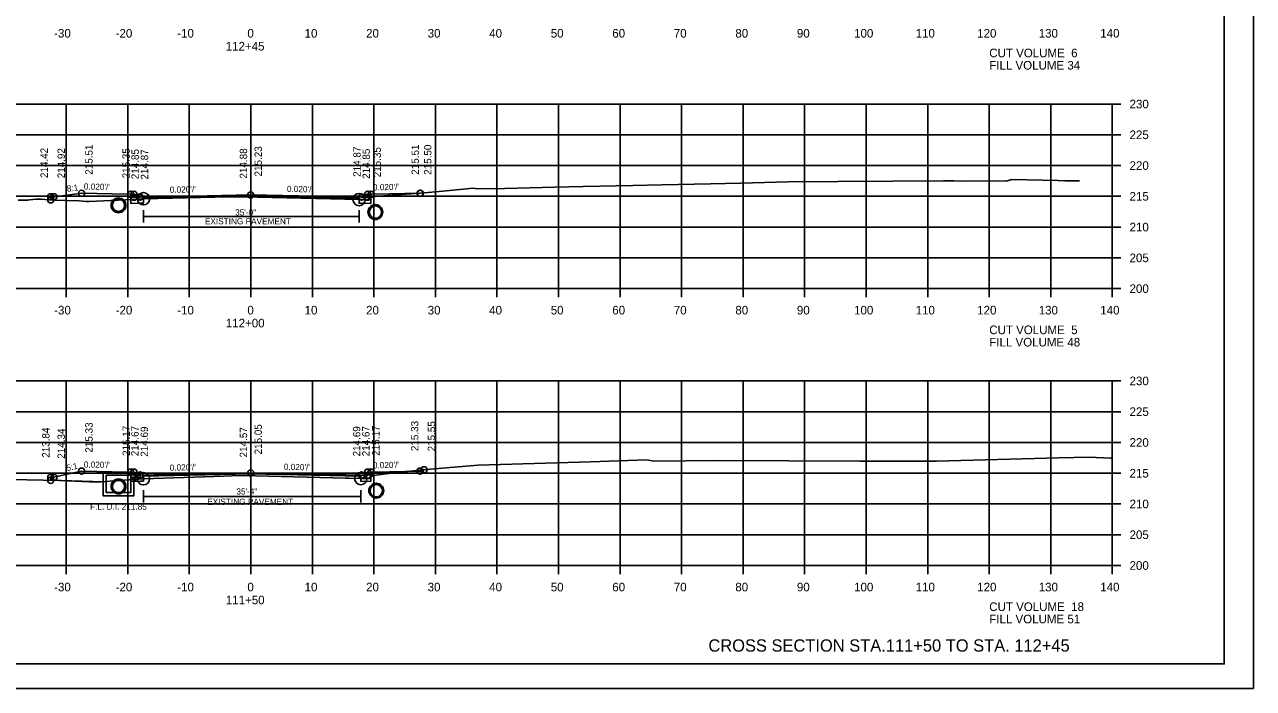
# Model space of a CAD drawing. Extents: x 1368968 to 1369915, y 377395 to 380381.
# Drawn here: x 1369715 to 1369914.7, y 377608 to 377715.9 of the extents above; entities that cross this region are included whole.
import ezdxf

# ---------------------------------------------------------------- set-up
doc = ezdxf.new("R2010")
doc.units = 0
for name, color, linetype in [('Default', 7, 'Continuous'), ('S_BORDER_NO_PLOT', 7, 'Continuous'), ('S_BREAKLINE_ANNOT', 7, 'Continuous'), ('S_BRIDGE', 7, 'Continuous'), ('S_BRIDGE_ANNOT', 7, 'Continuous'), ('S_CONTOUR_MINOR', 7, 'Continuous'), ('S_CROSS_DRAIN', 7, 'Continuous'), ('S_CTL_TABLE', 7, 'Continuous'), ('S_CURB_ANNOT', 7, 'Continuous'), ('S_DITCHLINE_ANNOT', 7, 'Continuous'), ('S_DROP_INLET', 7, 'Continuous'), ('S_EXIST_ROW_ANNOT', 7, 'Continuous'), ('S_EXISTING_ALIGNMENT_ANNOT', 7, 'Continuous'), ('S_FENCE', 7, 'Continuous')]:
    doc.layers.add(name, color=color, linetype=linetype)

msp = doc.modelspace()

# ---------------------------------------------------------------- linework, layer by layer
at = {"layer": 'Default'}
for p, q in [((1369734.35, 377687.73), (1369734.35, 377686.9)), ((1369734.32, 377642.55), (1369734.32, 377641.72))]:
    msp.add_line(p, q, dxfattribs=at)
at = {"layer": 'S_BORDER_NO_PLOT'}
for points in [[(1369732.27, 377688.36), (1369732.28, 377686.85), (1369733.78, 377686.88), (1369734.35, 377686.9), (1369734.35, 377687.73), (1369751.78, 377688.07), (1369769.37, 377687.72), (1369769.37, 377686.89), (1369769.78, 377686.88), (1369771.28, 377686.85), (1369771.29, 377688.36)], [(1369732.27, 377643.19), (1369732.28, 377641.68), (1369733.78, 377641.71), (1369734.32, 377641.72), (1369734.32, 377642.55), (1369751.78, 377642.9), (1369769.64, 377642.54), (1369769.64, 377641.71), (1369769.78, 377641.71), (1369771.28, 377641.68), (1369771.29, 377643.19)]]:
    msp.add_lwpolyline(points, dxfattribs=at)
at = {"layer": 'S_BREAKLINE_ANNOT'}
for p, q in [((1369891.78, 377673.01), (1369891.78, 377703.01)), ((1369893.18, 377703.01), (1369891.78, 377703.01)), ((1369893.18, 377698.01), (1369891.78, 377698.01)), ((1369893.18, 377693.01), (1369891.78, 377693.01)), ((1369893.18, 377688.01), (1369891.78, 377688.01)), ((1369893.18, 377683.01), (1369891.78, 377683.01)), ((1369893.18, 377678.01), (1369891.78, 377678.01)), ((1369611.78, 377673.01), (1369891.78, 377673.01)), ((1369721.78, 377671.61), (1369721.78, 377673.01)), ((1369731.78, 377671.61), (1369731.78, 377673.01)), ((1369741.78, 377671.61), (1369741.78, 377673.01)), ((1369751.78, 377671.61), (1369751.78, 377673.01)), ((1369761.78, 377671.61), (1369761.78, 377673.01)), ((1369771.78, 377671.61), (1369771.78, 377673.01)), ((1369781.78, 377671.61), (1369781.78, 377673.01)), ((1369791.78, 377671.61), (1369791.78, 377673.01)), ((1369801.78, 377671.61), (1369801.78, 377673.01)), ((1369811.78, 377671.61), (1369811.78, 377673.01)), ((1369821.78, 377671.61), (1369821.78, 377673.01)), ((1369831.78, 377671.61), (1369831.78, 377673.01)), ((1369841.78, 377671.61), (1369841.78, 377673.01)), ((1369851.78, 377671.61), (1369851.78, 377673.01)), ((1369861.78, 377671.61), (1369861.78, 377673.01)), ((1369871.78, 377671.61), (1369871.78, 377673.01)), ((1369881.78, 377671.61), (1369881.78, 377673.01)), ((1369891.78, 377671.61), (1369891.78, 377673.01)), ((1369893.18, 377673.01), (1369891.78, 377673.01)), ((1369891.78, 377628.01), (1369891.78, 377658.01)), ((1369893.18, 377658.01), (1369891.78, 377658.01)), ((1369893.18, 377653.01), (1369891.78, 377653.01)), ((1369893.18, 377648.01), (1369891.78, 377648.01)), ((1369893.18, 377643.01), (1369891.78, 377643.01)), ((1369893.18, 377638.01), (1369891.78, 377638.01)), ((1369893.18, 377633.01), (1369891.78, 377633.01)), ((1369611.78, 377628.01), (1369891.78, 377628.01)), ((1369721.78, 377626.61), (1369721.78, 377628.01)), ((1369731.78, 377626.61), (1369731.78, 377628.01)), ((1369741.78, 377626.61), (1369741.78, 377628.01)), ((1369751.78, 377626.61), (1369751.78, 377628.01)), ((1369761.78, 377626.61), (1369761.78, 377628.01)), ((1369771.78, 377626.61), (1369771.78, 377628.01)), ((1369781.78, 377626.61), (1369781.78, 377628.01)), ((1369791.78, 377626.61), (1369791.78, 377628.01)), ((1369801.78, 377626.61), (1369801.78, 377628.01)), ((1369811.78, 377626.61), (1369811.78, 377628.01)), ((1369821.78, 377626.61), (1369821.78, 377628.01)), ((1369831.78, 377626.61), (1369831.78, 377628.01)), ((1369841.78, 377626.61), (1369841.78, 377628.01)), ((1369851.78, 377626.61), (1369851.78, 377628.01)), ((1369861.78, 377626.61), (1369861.78, 377628.01)), ((1369871.78, 377626.61), (1369871.78, 377628.01)), ((1369881.78, 377626.61), (1369881.78, 377628.01)), ((1369891.78, 377626.61), (1369891.78, 377628.01)), ((1369893.18, 377628.01), (1369891.78, 377628.01))]:
    msp.add_line(p, q, dxfattribs=at)
at = {"layer": 'S_BRIDGE_ANNOT'}
for p, q in [((1369909.96, 377612.01), (1369909.96, 377817.47)), ((1369719.27, 377641.86), (1369727.8, 377641.62)), ((1369909.96, 377612.01), (1369593.78, 377612.01))]:
    msp.add_line(p, q, dxfattribs=at)
at = {"layer": 'S_CROSS_DRAIN'}
for p, q in [((1369734.35, 377684.74), (1369760.66, 377684.74)), ((1369734.35, 377684.74), (1369769.37, 377684.74)), ((1369734.32, 377639.25), (1369760.64, 377639.25)), ((1369734.32, 377639.25), (1369769.64, 377639.25))]:
    msp.add_line(p, q, dxfattribs=at)
at = {"layer": 'S_CTL_TABLE'}
for points in [[(1369713.95, 377687.36), (1369715.55, 377687.38), (1369715.81, 377687.42), (1369716.89, 377687.55), (1369717.76, 377687.53), (1369719.61, 377687.41), (1369723.9, 377687.26), (1369725.06, 377687.15), (1369725.53, 377687.18), (1369731.41, 377687.43), (1369734.35, 377687.61), (1369745.94, 377687.86), (1369750.46, 377687.93), (1369764.74, 377687.58), (1369769.37, 377687.49), (1369770.44, 377687.48), (1369770.77, 377687.48), (1369770.89, 377687.59), (1369771.32, 377687.95), (1369774.67, 377688.21), (1369777.05, 377688.34), (1369780.02, 377688.56), (1369782.96, 377688.87), (1369787.89, 377689.32), (1369788.58, 377689.21), (1369792.98, 377689.3), (1369801.21, 377689.49), (1369805.78, 377689.59), (1369813.85, 377689.78), (1369818.57, 377689.88), (1369826.5, 377690.06), (1369831.35, 377690.16), (1369839.15, 377690.34), (1369847.19, 377690.41), (1369856.12, 377690.47), (1369864.35, 377690.54), (1369866.02, 377690.55), (1369867.22, 377690.5), (1369873.49, 377690.54), (1369874.53, 377690.5), (1369875.45, 377690.74), (1369882.94, 377690.56), (1369884.05, 377690.51), (1369885.7, 377690.51), (1369886.42, 377690.52)], [(1369712.75, 377642.01), (1369720.68, 377641.83), (1369720.75, 377641.82), (1369720.77, 377641.82), (1369726.78, 377641.56), (1369728.9, 377641.71), (1369734.32, 377642.12), (1369747.38, 377642.53), (1369750, 377642.62), (1369752.6, 377642.57), (1369767.16, 377642.21), (1369767.72, 377642.2), (1369769.64, 377642.14), (1369770.79, 377642.15), (1369771.01, 377642.15), (1369771.58, 377642.56), (1369771.69, 377642.64), (1369773.75, 377642.89), (1369779.7, 377643.54), (1369788.06, 377644.29), (1369788.66, 377644.34), (1369790.52, 377644.39), (1369806.99, 377644.88), (1369816.16, 377645.17), (1369817.29, 377644.97), (1369827.65, 377645.06), (1369850.77, 377644.97), (1369863.22, 377644.99), (1369883.11, 377645.52), (1369888.01, 377645.63), (1369891.47, 377645.48), (1369891.78, 377645.47)]]:
    msp.add_lwpolyline(points, dxfattribs=at)
at = {"layer": 'S_CURB_ANNOT'}
for points in [[(1369719.27, 377687.44), (1369719.27, 377687.94), (1369719.77, 377687.94), (1369721.57, 377688.17), (1369724.27, 377688.52), (1369729.27, 377688.42), (1369732.27, 377688.36), (1369732.42, 377688.36), (1369732.77, 377688.36), (1369732.78, 377687.86), (1369733.78, 377687.88), (1369733.78, 377687.88), (1369744.69, 377688.1), (1369751.78, 377688.24), (1369769.78, 377687.88), (1369770.78, 377687.86), (1369770.78, 377688.22), (1369770.79, 377688.36), (1369770.82, 377688.36), (1369771.29, 377688.36), (1369774.29, 377688.42), (1369779.29, 377688.52), (1369779.32, 377688.51), (1369779.33, 377688.51)], [(1369719.27, 377641.86), (1369719.27, 377642.36), (1369719.77, 377642.36), (1369721.94, 377642.84), (1369724.27, 377643.35), (1369729.27, 377643.25), (1369732.27, 377643.19), (1369732.4, 377643.19), (1369732.77, 377643.19), (1369732.78, 377642.69), (1369733.78, 377642.71), (1369745.28, 377642.94), (1369751.77, 377643.07), (1369751.78, 377643.07), (1369769.78, 377642.71), (1369770.78, 377642.69), (1369770.78, 377642.88), (1369770.79, 377643.19), (1369770.86, 377643.19), (1369771.29, 377643.19), (1369774.29, 377643.25), (1369779.29, 377643.35), (1369779.93, 377643.56)]]:
    msp.add_lwpolyline(points, dxfattribs=at)
at = {"layer": 'S_DITCHLINE_ANNOT'}
for p, q in [((1369611.78, 377703.01), (1369891.78, 377703.01)), ((1369721.78, 377673.01), (1369721.78, 377703.01)), ((1369731.78, 377673.01), (1369731.78, 377703.01)), ((1369741.78, 377673.01), (1369741.78, 377703.01)), ((1369751.78, 377673.01), (1369751.78, 377703.01)), ((1369761.78, 377673.01), (1369761.78, 377703.01)), ((1369771.78, 377673.01), (1369771.78, 377703.01)), ((1369781.78, 377673.01), (1369781.78, 377703.01)), ((1369791.78, 377673.01), (1369791.78, 377703.01)), ((1369801.78, 377673.01), (1369801.78, 377703.01)), ((1369811.78, 377673.01), (1369811.78, 377703.01)), ((1369821.78, 377673.01), (1369821.78, 377703.01)), ((1369831.78, 377673.01), (1369831.78, 377703.01)), ((1369841.78, 377673.01), (1369841.78, 377703.01)), ((1369851.78, 377673.01), (1369851.78, 377703.01)), ((1369861.78, 377673.01), (1369861.78, 377703.01)), ((1369871.78, 377673.01), (1369871.78, 377703.01)), ((1369881.78, 377673.01), (1369881.78, 377703.01)), ((1369891.78, 377673.01), (1369891.78, 377703.01)), ((1369611.78, 377698.01), (1369891.78, 377698.01)), ((1369611.78, 377693.01), (1369891.78, 377693.01)), ((1369611.78, 377688.01), (1369891.78, 377688.01)), ((1369611.78, 377683.01), (1369891.78, 377683.01)), ((1369611.78, 377678.01), (1369891.78, 377678.01)), ((1369611.78, 377673.01), (1369891.78, 377673.01)), ((1369611.78, 377658.01), (1369891.78, 377658.01)), ((1369721.78, 377628.01), (1369721.78, 377658.01)), ((1369731.78, 377628.01), (1369731.78, 377658.01)), ((1369741.78, 377628.01), (1369741.78, 377658.01)), ((1369751.78, 377628.01), (1369751.78, 377658.01)), ((1369761.78, 377628.01), (1369761.78, 377658.01)), ((1369771.78, 377628.01), (1369771.78, 377658.01)), ((1369781.78, 377628.01), (1369781.78, 377658.01)), ((1369791.78, 377628.01), (1369791.78, 377658.01)), ((1369801.78, 377628.01), (1369801.78, 377658.01)), ((1369811.78, 377628.01), (1369811.78, 377658.01)), ((1369821.78, 377628.01), (1369821.78, 377658.01)), ((1369831.78, 377628.01), (1369831.78, 377658.01)), ((1369841.78, 377628.01), (1369841.78, 377658.01)), ((1369851.78, 377628.01), (1369851.78, 377658.01)), ((1369861.78, 377628.01), (1369861.78, 377658.01)), ((1369871.78, 377628.01), (1369871.78, 377658.01)), ((1369881.78, 377628.01), (1369881.78, 377658.01)), ((1369891.78, 377628.01), (1369891.78, 377658.01)), ((1369611.78, 377653.01), (1369891.78, 377653.01)), ((1369611.78, 377648.01), (1369891.78, 377648.01)), ((1369611.78, 377643.01), (1369891.78, 377643.01)), ((1369611.78, 377638.01), (1369891.78, 377638.01)), ((1369611.78, 377633.01), (1369891.78, 377633.01)), ((1369611.78, 377628.01), (1369891.78, 377628.01))]:
    msp.add_line(p, q, dxfattribs=at)
at = {"layer": 'S_DROP_INLET'}
for p, q in [((1369730.28, 377642.07), (1369730.28, 377642.01)), ((1369730.28, 377639.66), (1369730.28, 377639.59)), ((1369581.38, 377608.04), (1369914.71, 377608.04))]:
    msp.add_line(p, q, dxfattribs=at)
for points in [[(1369581.37, 377821.37), (1369914.71, 377821.37), (1369914.71, 377608.03), (1369581.37, 377608.03)], [(1369827.7, 377817.47), (1369827.7, 377807.59), (1369863.43, 377807.59), (1369863.43, 377804.67), (1369886.63, 377804.67), (1369886.63, 377780.34), (1369909.96, 377780.34), (1369909.96, 377612.01), (1369593.78, 377612.01), (1369593.78, 377817.47)]]:
    msp.add_lwpolyline(points, close=True, dxfattribs=at)
for centre, radius in [((1369719.27, 377687.94), 0.5), ((1369719.27, 377687.44), 0.5), ((1369719.77, 377687.94), 0.5), ((1369724.27, 377688.52), 0.5), ((1369730.28, 377686.55), 1.21), ((1369732.27, 377688.36), 0.5), ((1369732.77, 377688.36), 0.5), ((1369732.78, 377687.86), 0.5), ((1369733.78, 377687.88), 0.5), ((1369733.78, 377687.88), 0.5), ((1369734.35, 377687.61), 1), ((1369751.78, 377688.24), 0.5), ((1369769.37, 377687.49), 1), ((1369769.78, 377687.88), 0.5), ((1369769.78, 377687.88), 0.5), ((1369770.78, 377687.86), 0.5), ((1369770.79, 377688.36), 0.5), ((1369771.29, 377688.36), 0.5), ((1369779.29, 377688.52), 0.5), ((1369779.33, 377688.51), 0.5), ((1369779.33, 377688.51), 0.5), ((1369772.02, 377685.45), 1.21), ((1369724.27, 377643.35), 0.5), ((1369732.27, 377643.19), 0.5), ((1369732.77, 377643.19), 0.5), ((1369751.78, 377643.07), 0.5), ((1369770.79, 377643.19), 0.5), ((1369771.29, 377643.19), 0.5), ((1369779.29, 377643.35), 0.5), ((1369779.93, 377643.56), 0.5), ((1369719.27, 377642.36), 0.5), ((1369719.27, 377641.86), 0.5), ((1369719.77, 377642.36), 0.5), ((1369730.28, 377640.86), 1.21), ((1369730.28, 377640.86), 1.21), ((1369732.78, 377642.69), 0.5), ((1369733.78, 377642.71), 0.5), ((1369733.78, 377642.71), 0.5), ((1369734.32, 377642.12), 1), ((1369769.64, 377642.14), 1), ((1369769.78, 377642.71), 0.5), ((1369769.78, 377642.71), 0.5), ((1369770.78, 377642.69), 0.5), ((1369772.17, 377640.17), 1.21)]:
    msp.add_circle(centre, radius, dxfattribs=at)
at = {"layer": 'S_EXIST_ROW_ANNOT'}
for p, q in [((1369734.35, 377683.74), (1369734.35, 377685.74)), ((1369734.35, 377683.74), (1369734.35, 377685.74)), ((1369769.37, 377683.74), (1369769.37, 377685.74)), ((1369771.99, 377686.72), (1369772.05, 377686.6)), ((1369771.99, 377686.51), (1369772.05, 377686.4)), ((1369771.99, 377684.51), (1369772.05, 377684.4)), ((1369771.99, 377684.3), (1369772.05, 377684.19)), ((1369727.78, 377643.18), (1369732.53, 377643.18)), ((1369727.78, 377641.68), (1369727.78, 377643.18)), ((1369728.28, 377641.68), (1369728.28, 377642.68)), ((1369728.28, 377642.68), (1369732.28, 377642.68)), ((1369730.28, 377641.86), (1369730.28, 377641.8)), ((1369732.61, 377643.02), (1369732.28, 377642.68)), ((1369733.78, 377642.7), (1369732.28, 377642.18)), ((1369732.28, 377641.68), (1369732.28, 377642.18)), ((1369732.61, 377643.02), (1369732.53, 377643.18)), ((1369733.78, 377642.18), (1369732.78, 377641.83)), ((1369732.78, 377641.68), (1369732.78, 377641.83)), ((1369730.28, 377639.86), (1369730.28, 377639.8)), ((1369734.32, 377638.25), (1369734.32, 377640.25)), ((1369734.32, 377638.25), (1369734.32, 377640.25)), ((1369769.64, 377638.25), (1369769.64, 377640.25)), ((1369772.14, 377641.44), (1369772.2, 377641.33)), ((1369772.14, 377641.23), (1369772.2, 377641.12)), ((1369772.14, 377639.23), (1369772.2, 377639.12)), ((1369772.14, 377639.02), (1369772.2, 377638.91))]:
    msp.add_line(p, q, dxfattribs=at)
for points in [[(1369732.78, 377641.68), (1369732.78, 377639.36), (1369730.28, 377639.36), (1369727.78, 377639.36), (1369727.78, 377641.68)], [(1369732.28, 377641.68), (1369732.28, 377639.86), (1369730.28, 377639.86), (1369728.28, 377639.86), (1369728.28, 377641.68)], [(1369733.78, 377642.18), (1369733.78, 377642.7)]]:
    msp.add_lwpolyline(points, dxfattribs=at)
for centre in [(1369730.28, 377686.55), (1369772.02, 377685.45), (1369730.28, 377640.86), (1369730.28, 377640.86), (1369772.17, 377640.17)]:
    msp.add_circle(centre, 1, dxfattribs=at)
at = {"layer": 'S_EXISTING_ALIGNMENT_ANNOT'}
for p, q in [((1369751.78, 377687.9), (1369751.78, 377697.9)), ((1369751.78, 377642.58), (1369751.78, 377652.58))]:
    msp.add_line(p, q, dxfattribs=at)

# ---------------------------------------------------------------- texts
at = {"layer": 'S_BRIDGE'}
for s, p in [('-30', (1369719.82, 377713.81)), ('-20', (1369729.82, 377713.81)), ('-10', (1369739.82, 377713.81)), ('0', (1369751.22, 377713.81)), ('10', (1369760.52, 377713.81)), ('20', (1369770.52, 377713.81)), ('30', (1369780.52, 377713.81)), ('40', (1369790.52, 377713.81)), ('50', (1369800.52, 377713.81)), ('60', (1369810.52, 377713.81)), ('70', (1369820.52, 377713.81)), ('80', (1369830.52, 377713.81)), ('90', (1369840.52, 377713.81)), ('100', (1369849.82, 377713.81)), ('110', (1369859.82, 377713.81)), ('120', (1369869.82, 377713.81)), ('130', (1369879.82, 377713.81)), ('140', (1369889.82, 377713.81)), ('112+45', (1369747.7, 377711.71)), ('CUT VOLUME  6', (1369871.78, 377710.61)), ('FILL VOLUME 34', (1369871.78, 377708.61)), ('230', (1369894.58, 377702.31)), ('225', (1369894.58, 377697.31)), ('220', (1369894.58, 377692.31)), ('215', (1369894.58, 377687.31)), ('210', (1369894.58, 377682.31)), ('205', (1369894.58, 377677.31)), ('200', (1369894.58, 377672.31)), ('-30', (1369719.82, 377668.81)), ('-20', (1369729.82, 377668.81)), ('-10', (1369739.82, 377668.81)), ('0', (1369751.22, 377668.81)), ('10', (1369760.52, 377668.81)), ('20', (1369770.52, 377668.81)), ('30', (1369780.52, 377668.81)), ('40', (1369790.52, 377668.81)), ('50', (1369800.52, 377668.81)), ('60', (1369810.52, 377668.81)), ('70', (1369820.52, 377668.81)), ('80', (1369830.52, 377668.81)), ('90', (1369840.52, 377668.81)), ('100', (1369849.82, 377668.81)), ('110', (1369859.82, 377668.81)), ('120', (1369869.82, 377668.81)), ('130', (1369879.82, 377668.81)), ('140', (1369889.82, 377668.81)), ('112+00', (1369747.72, 377666.71)), ('CUT VOLUME  5', (1369871.78, 377665.61)), ('FILL VOLUME 48', (1369871.78, 377663.61)), ('230', (1369894.58, 377657.31)), ('225', (1369894.58, 377652.31)), ('220', (1369894.58, 377647.31)), ('215', (1369894.58, 377642.31)), ('210', (1369894.58, 377637.31)), ('205', (1369894.58, 377632.31)), ('200', (1369894.58, 377627.31)), ('-30', (1369719.82, 377623.81)), ('-20', (1369729.82, 377623.81)), ('-10', (1369739.82, 377623.81)), ('0', (1369751.22, 377623.81)), ('10', (1369760.52, 377623.81)), ('20', (1369770.52, 377623.81)), ('30', (1369780.52, 377623.81)), ('40', (1369790.52, 377623.81)), ('50', (1369800.52, 377623.81)), ('60', (1369810.52, 377623.81)), ('70', (1369820.52, 377623.81)), ('80', (1369830.52, 377623.81)), ('90', (1369840.52, 377623.81)), ('100', (1369849.82, 377623.81)), ('110', (1369859.82, 377623.81)), ('120', (1369869.82, 377623.81)), ('130', (1369879.82, 377623.81)), ('140', (1369889.82, 377623.81)), ('111+50', (1369747.72, 377621.71)), ('CUT VOLUME  18', (1369871.78, 377620.61)), ('FILL VOLUME 51', (1369871.78, 377618.61))]:
    msp.add_text(s, height=1.4, dxfattribs=at).set_placement(p)
at = {"layer": 'S_CONTOUR_MINOR'}
msp.add_text('CROSS SECTION STA.111+50 TO STA. 112+45', height=2, dxfattribs=at).set_placement((1369826.14, 377614.01))
at = {"layer": 'S_EXIST_ROW_ANNOT'}
for s, p in [('35\'-0"', (1369749.24, 377684.9)), ('EXISTING PAVEMENT', (1369744.32, 377683.46)), ('35\'-4"', (1369749.43, 377639.55)), ('F.L. D.I. 211.85', (1369725.66, 377637.07)), ('EXISTING PAVEMENT', (1369744.69, 377637.87))]:
    msp.add_text(s, height=1, dxfattribs=at).set_placement(p)
at = {"layer": 'S_EXISTING_ALIGNMENT_ANNOT'}
for s, p in [('214.42', (1369718.8, 377690.98)), ('214.92', (1369721.57, 377690.94)), ('215.51', (1369726.07, 377691.52)), ('215.35', (1369732.11, 377690.93)), ('214.85', (1369733.58, 377690.79)), ('214.87', (1369735.1, 377690.74)), ('214.88', (1369751.18, 377690.9)), ('215.23', (1369753.58, 377691.24)), ('214.87', (1369769.64, 377691.18)), ('214.85', (1369771.13, 377690.85)), ('215.35', (1369772.91, 377691.1)), ('215.51', (1369779.1, 377691.52)), ('215.50', (1369781.13, 377691.51)), ('215.50', (1369781.13, 377691.51)), ('213.84', (1369719.07, 377645.52)), ('214.34', (1369721.57, 377645.36)), ('215.33', (1369726.07, 377646.35)), ('215.17', (1369732.14, 377645.82)), ('214.67', (1369733.55, 377645.78)), ('214.69', (1369735.07, 377645.69)), ('214.57', (1369751.18, 377645.58)), ('215.05', (1369753.58, 377646.07)), ('214.69', (1369769.57, 377645.74)), ('214.67', (1369771.07, 377645.76)), ('215.17', (1369772.7, 377645.84)), ('215.33', (1369779.01, 377646.6)), ('215.55', (1369781.73, 377646.56))]:
    msp.add_text(s, height=1.2, rotation=90, dxfattribs=at).set_placement(p)
at = {"layer": 'S_FENCE'}
for s, rotation, p in [('8:1', 7.4315, (1369721.95, 377688.73)), ("0.020'/'", 358.8543, (1369724.63, 377689.12)), ("0.020'/'", 1.1457, (1369738.62, 377688.58)), ("0.020'/'", 358.8542, (1369757.64, 377688.73)), ("0.020'/'", 1.1457, (1369771.63, 377688.97)), ('5:1', 12.4188, (1369721.91, 377643.34)), ("0.020'/'", 358.8542, (1369724.63, 377643.94)), ("0.020'/'", 1.1457, (1369738.61, 377643.41)), ("0.020'/'", 358.8542, (1369757.14, 377643.56)), ("0.020'/'", 1.1457, (1369771.63, 377643.8))]:
    msp.add_text(s, height=1, rotation=rotation, dxfattribs=at).set_placement(p)

doc.saveas('drawing.dxf')
